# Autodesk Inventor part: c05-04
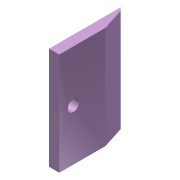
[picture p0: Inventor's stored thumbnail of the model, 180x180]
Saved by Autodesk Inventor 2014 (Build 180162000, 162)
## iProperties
Created: 2010-11
Part Number: c05-04
Material: Generic
Document SubType Name: Modeling
Designer: Thom Tremblay
Density: 1 g/cm^3
Appearance: Satin - Lavender
Author: Thom Tremblay
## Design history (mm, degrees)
sketch "Sketch1"
  geometry: L1 (0, 0)-(10, 0); L2 (10, 0)-(10, 70); L3 (10, 70)-(0, 70); L4 (0, 70)-(0, 0); L5 (3, 67)-(10, 45); L6 (0, 70)-(3, 67); 1 further point
  constraints: 12 end point, 2 parallel, 2 point on line, 1 horizontal, 1 perpendicular
  dimensions: "d0" = 10 distance of L3.end L2.end; "d1" = 70 distance of L2.end L1.end; "d3" = 25 vertical distance of point (2.045, 70) L5.end; "d6" = 45 deg angle of L4 L6; "d7" = 3 distance from line of L4 L5.start
extrude "Extrusion1" new body sketch "Sketch1" stored distance "d4" = 100; taper "d5" = 0 deg
hole "Hole1" diameter "d10" = 11; stored, may be unused: countersink angle "d14" = 90 deg, drill point angle "d16" = 118 deg; dims "d8" = 50, "d9" = 13.8, "d11" = 6, "d12" = 4, "d13" = 90, "d15" = 8
body "Solid1"
